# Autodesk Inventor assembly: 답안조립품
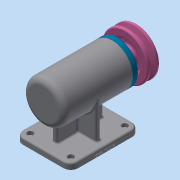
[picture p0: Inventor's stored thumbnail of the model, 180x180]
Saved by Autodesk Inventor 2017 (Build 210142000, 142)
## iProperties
Part Number: 답안조립품
Material: 일반
Document SubType Name: Assembly
Designer: 222
Author: 222
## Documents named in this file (12)
- C:\Users\222\Desktop\701004V1028\답안조립품.iam
- C:\Users\222\Desktop\701004V1028\본체.ipt
- C:\Users\222\Desktop\701004V1028\Ű 5 x 5 x 16.ipt
- C:\Users\222\Desktop\701004V1028\V벨트풀리.ipt
- C:\Users\222\Desktop\701004V1028\멈춤나사 M3.ipt
- C:\Users\222\Desktop\701004V1028\베어링 6004.ipt
- C:\Users\222\Desktop\701004V1028\베어링 51202.ipt
- C:\Users\222\Desktop\701004V1028\볼트 M4.ipt
- C:\Users\222\Desktop\701004V1028\어댑터슬리브.ipt
- C:\Users\222\Desktop\701004V1028\오일 실.ipt
- C:\Users\222\Desktop\701004V1028\축.ipt
- C:\Users\222\Desktop\701004V1028\커버.ipt
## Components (2 placed, 2 different names)
1. Ű 5 x 5 x 16:1
2. V벨트풀리:1 — 플러쉬:1
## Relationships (1: Flush 1)
- 플러쉬:1 [Flush]: V벨트풀리:1
